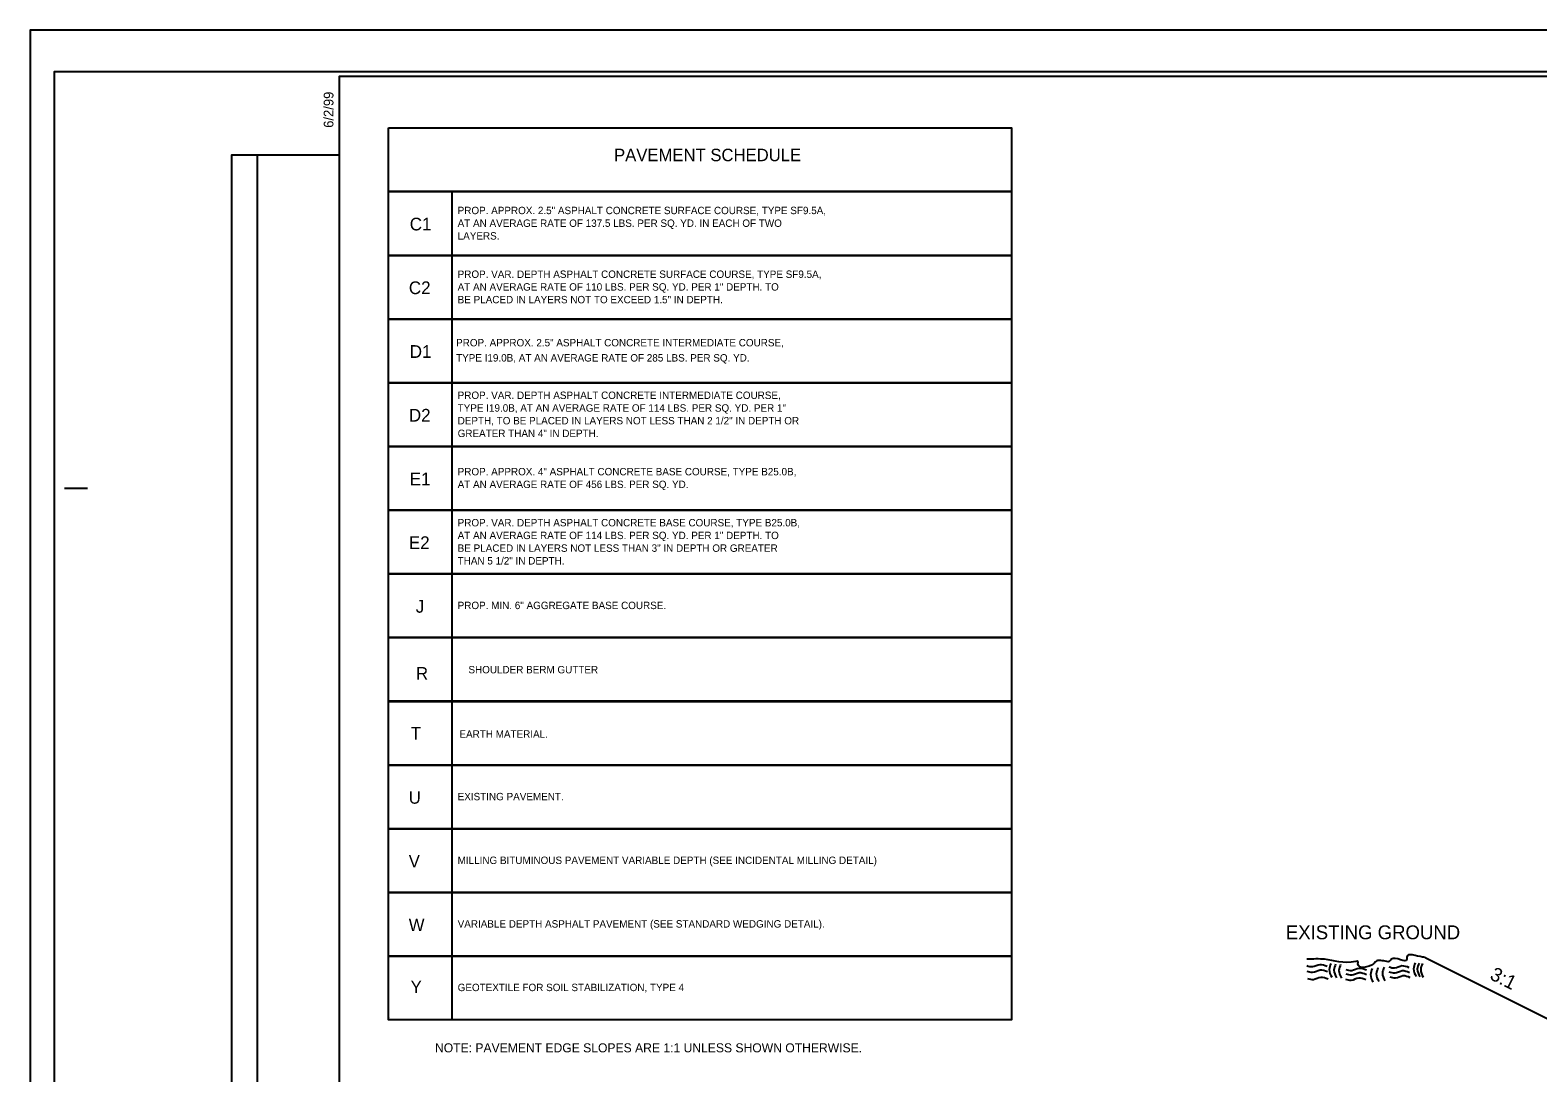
# Model space of a CAD drawing. Extents: x 575722 to 576066, y -53107 to -52774.
# Drawn here: x 575797.4 to 575878.8, y -53053.2 to -52996.9 of the extents above; entities that cross this region are included whole.
import ezdxf

# ---------------------------------------------------------------- set-up
doc = ezdxf.new("R2010")
doc.units = 0
for name, color, linetype in [('Old_Level_19', 7, 'Continuous'), ('Old_Level_2', 7, 'Continuous'), ('Prop DSN Text', 7, 'Continuous'), ('Prop Pavement Schedule Description CELL', 7, 'Continuous'), ('Sheet Block Revision CELL', 7, 'Continuous'), ('Sheet Cutting Line CELL', 7, 'Continuous'), ('Sheet Plot Border Inside CELL', 7, 'Continuous'), ('Sheet Plot Border Outside CELL', 7, 'Continuous'), ('Sheet Typical CELL', 7, 'Continuous'), ('Typical Slope Point Local CELL', 7, 'Continuous'), ('Typical Text Grade Point CELL', 7, 'Continuous')]:
    doc.layers.add(name, color=color, linetype=linetype)

# ---------------------------------------------------------------- blocks, each defined once
blk = doc.blocks.new('Note Standard Slope')
at = {"layer": 'Prop Pavement Schedule Description CELL'}
blk.add_line((0, 0), (0, 0), dxfattribs=at)
blk.add_text('NOTE: PAVEMENT EDGE SLOPES ARE 1:1 UNLESS SHOWN OTHERWISE.', height=5.4417, dxfattribs=at).set_placement((27.18, -20.66))

msp = doc.modelspace()

# ---------------------------------------------------------------- linework, layer by layer
at = {"layer": 'Old_Level_19'}
msp.add_lwpolyline([(575820.174, -53033.124), (575816.739, -53033.124), (575816.739, -53029.689), (575850.399, -53029.689), (575850.399, -53033.124), (575820.174, -53033.124), (575820.174, -53029.689)], dxfattribs=at)
at = {"layer": 'Old_Level_2'}
for points in [[(575872.735, -53046.963), (575872.592, -53046.948), (575871.752, -53046.948), (575871.752, -53047.068), (575870.912, -53047.068), (575870.792, -53047.188), (575870.672, -53047.188), (575870.072, -53047.188), (575869.952, -53047.308), (575869.112, -53047.308), (575869.112, -53047.188), (575868.992, -53047.188), (575867.312, -53047.068), (575866.356, -53047.068)], [(575867.444, -53047.456), (575867.055, -53047.362), (575866.651, -53047.483), (575866.356, -53047.429)], [(575867.653, -53047.301), (575867.559, -53047.624), (575867.693, -53048.041)], [(575867.908, -53047.328), (575867.814, -53047.651), (575867.949, -53048.068)], [(575868.177, -53047.342), (575868.083, -53047.664), (575868.217, -53048.081)], [(575869.568, -53047.658), (575869.178, -53047.564), (575868.775, -53047.684), (575868.479, -53047.631)], [(575869.884, -53047.57), (575869.79, -53047.893), (575869.924, -53048.309)], [(575870.193, -53047.53), (575870.099, -53047.852), (575870.233, -53048.269)], [(575870.529, -53047.489), (575870.435, -53047.812), (575870.569, -53048.229)], [(575871.88, -53047.523), (575871.49, -53047.429), (575871.087, -53047.55), (575870.791, -53047.496)], [(575872.209, -53047.261), (575872.115, -53047.584), (575872.249, -53048)], [(575872.411, -53047.274), (575872.317, -53047.597), (575872.451, -53048.014)], [(575872.599, -53047.301), (575872.505, -53047.624), (575872.639, -53048.041)], [(575867.458, -53047.752), (575867.068, -53047.658), (575866.665, -53047.779), (575866.369, -53047.725)], [(575867.498, -53048.141), (575867.108, -53048.047), (575866.705, -53048.168), (575866.409, -53048.115)], [(575869.541, -53048.182), (575869.151, -53048.088), (575868.748, -53048.209), (575868.452, -53048.155)], [(575869.568, -53047.9), (575869.178, -53047.805), (575868.775, -53047.926), (575868.479, -53047.873)], [(575871.893, -53047.792), (575871.503, -53047.698), (575871.1, -53047.819), (575870.805, -53047.765)], [(575871.934, -53048.061), (575871.544, -53047.967), (575871.141, -53048.088), (575870.845, -53048.034)]]:
    msp.add_spline(points, degree=3, dxfattribs=at)
at = {"layer": 'Prop Pavement Schedule Description CELL'}
msp.add_lwpolyline([(575816.739, -53002.148), (575850.4, -53002.148), (575850.4, -53005.591), (575816.739, -53005.591)], close=True, dxfattribs=at)
for points in [[(575820.182, -53009.034), (575816.739, -53009.034), (575816.739, -53005.591), (575850.399, -53005.591), (575850.399, -53009.034), (575820.182, -53009.034), (575820.182, -53005.591)], [(575820.182, -53012.476), (575816.739, -53012.476), (575816.739, -53009.034), (575850.399, -53009.034), (575850.399, -53012.476), (575820.182, -53012.476), (575820.182, -53009.034)], [(575820.182, -53015.919), (575816.739, -53015.919), (575816.739, -53012.476), (575850.399, -53012.476), (575850.399, -53015.919), (575820.182, -53015.919), (575820.182, -53012.476)], [(575820.182, -53019.361), (575816.739, -53019.361), (575816.739, -53015.919), (575850.4, -53015.919), (575850.4, -53019.361), (575820.182, -53019.361), (575820.182, -53015.919)], [(575820.182, -53022.804), (575816.739, -53022.804), (575816.739, -53019.361), (575850.399, -53019.361), (575850.399, -53022.804), (575820.182, -53022.804), (575820.182, -53019.361)], [(575820.182, -53026.246), (575816.739, -53026.246), (575816.739, -53022.804), (575850.399, -53022.804), (575850.399, -53026.246), (575820.182, -53026.246), (575820.182, -53022.804)], [(575820.182, -53029.689), (575816.739, -53029.689), (575816.739, -53026.246), (575850.399, -53026.246), (575850.399, -53029.689), (575820.182, -53029.689), (575820.182, -53026.246)], [(575820.182, -53036.573), (575816.739, -53036.573), (575816.739, -53033.131), (575850.399, -53033.131), (575850.399, -53036.573), (575820.182, -53036.573), (575820.182, -53033.131)], [(575820.182, -53040.016), (575816.739, -53040.016), (575816.739, -53036.573), (575850.399, -53036.573), (575850.399, -53040.016), (575820.182, -53040.016), (575820.182, -53036.573)], [(575820.182, -53043.458), (575816.739, -53043.458), (575816.739, -53040.016), (575850.399, -53040.016), (575850.399, -53043.458), (575820.182, -53043.458), (575820.182, -53040.016)], [(575820.182, -53046.901), (575816.739, -53046.901), (575816.739, -53043.458), (575850.4, -53043.458), (575850.4, -53046.901), (575820.182, -53046.901), (575820.182, -53043.458)], [(575820.182, -53050.343), (575816.739, -53050.343), (575816.739, -53046.901), (575850.4, -53046.901), (575850.4, -53050.343), (575820.182, -53050.343), (575820.182, -53046.901)]]:
    msp.add_lwpolyline(points, dxfattribs=at)
at = {"layer": 'Sheet Block Revision CELL'}
msp.add_line((575809.664, -53079.514), (575809.664, -53003.612), dxfattribs=at)
msp.add_lwpolyline([(575808.268, -53079.514), (575808.268, -53003.612), (575814.08, -53003.612), (575814.08, -53079.514)], close=True, dxfattribs=at)
at = {"layer": 'Sheet Cutting Line CELL'}
for p, q in [((575965.78, -52996.867), (575797.38, -52996.867)), ((575797.38, -52996.867), (575797.38, -53106.867))]:
    msp.add_line(p, q, dxfattribs=at)
at = {"layer": 'Sheet Plot Border Inside CELL'}
msp.add_lwpolyline([(575965.33, -52999.112), (575798.68, -52999.112), (575798.68, -53104.622), (575965.33, -53104.622)], close=True, dxfattribs=at)
at = {"layer": 'Sheet Plot Border Outside CELL'}
msp.add_lwpolyline([(575965.78, -52996.867), (575797.38, -52996.867), (575797.38, -53106.867), (575965.78, -53106.867)], close=True, dxfattribs=at)
at = {"layer": 'Sheet Typical CELL'}
msp.add_line((575799.23, -53021.617), (575800.48, -53021.617), dxfattribs=at)
msp.add_lwpolyline([(575964.08, -52999.367), (575814.08, -52999.367), (575814.08, -53104.367), (575964.08, -53104.367)], close=True, dxfattribs=at)
at = {"layer": 'Typical Slope Point Local CELL'}
msp.add_line((575872.735, -53046.963), (575880.664, -53050.928), dxfattribs=at)

# ---------------------------------------------------------------- block references
at = {"layer": 'Prop DSN Text', "xscale": 0.09000000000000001, "yscale": 0.09000000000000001}
msp.add_blockref('Note Standard Slope', (575816.805, -53050.236), dxfattribs=at)

# ---------------------------------------------------------------- texts
at = {"layer": 'Prop Pavement Schedule Description CELL'}
for s, height, p in [('PAVEMENT SCHEDULE', 0.6732, (575828.925, -53003.947)), ('PROP. APPROX. 2.5" ASPHALT CONCRETE SURFACE COURSE, TYPE SF9.5A, ', 0.3995, (575820.476, -53006.808)), ('C1', 0.6872, (575817.887, -53007.687)), ('AT AN AVERAGE RATE OF 137.5 LBS. PER SQ. YD. IN EACH OF TWO ', 0.3995, (575820.476, -53007.495)), ('LAYERS.', 0.3995, (575820.476, -53008.181)), ('PROP. VAR. DEPTH ASPHALT CONCRETE SURFACE COURSE, TYPE SF9.5A,', 0.3995, (575820.476, -53010.252)), ('C2', 0.6872, (575817.839, -53011.13)), ('AT AN AVERAGE RATE OF 110 LBS. PER SQ. YD. PER 1" DEPTH. TO', 0.3995, (575820.476, -53010.938)), ('BE PLACED IN LAYERS NOT TO EXCEED 1.5" IN DEPTH.', 0.3995, (575820.476, -53011.625)), ('D1', 0.6872, (575817.887, -53014.573)), ('PROP. APPROX. 2.5" ASPHALT CONCRETE INTERMEDIATE COURSE,', 0.3995, (575820.392, -53013.952)), ('TYPE I19.0B, AT AN AVERAGE RATE OF 285 LBS. PER SQ. YD.', 0.3995, (575820.392, -53014.771)), ('PROP. VAR. DEPTH ASPHALT CONCRETE INTERMEDIATE COURSE,', 0.3995, (575820.476, -53016.793)), ('D2', 0.6872, (575817.839, -53018.015)), ('TYPE I19.0B, AT AN AVERAGE RATE OF 114 LBS. PER SQ. YD. PER 1" ', 0.3995, (575820.476, -53017.479)), ('DEPTH, TO BE PLACED IN LAYERS NOT LESS THAN 2 1/2" IN DEPTH OR', 0.3995, (575820.476, -53018.166)), ('GREATER THAN 4" IN DEPTH.', 0.3995, (575820.476, -53018.852)), ('PROP. APPROX. 4" ASPHALT CONCRETE BASE COURSE, TYPE B25.0B,', 0.3995, (575820.476, -53020.919)), ('E1', 0.6872, (575817.887, -53021.458)), ('AT AN AVERAGE RATE OF 456 LBS. PER SQ. YD.', 0.3995, (575820.476, -53021.606)), ('AT AN AVERAGE RATE OF 114 LBS. PER SQ. YD. PER 1" DEPTH. TO', 0.3995, (575820.476, -53024.364)), ('PROP. VAR. DEPTH ASPHALT CONCRETE BASE COURSE, TYPE B25.0B,', 0.3995, (575820.476, -53023.678)), ('E2', 0.6872, (575817.839, -53024.9)), ('BE PLACED IN LAYERS NOT LESS THAN 3" IN DEPTH OR GREATER', 0.3995, (575820.476, -53025.051)), ('THAN 5 1/2" IN DEPTH.', 0.3995, (575820.476, -53025.737)), ('J', 0.687, (575818.212, -53028.343)), ('PROP. MIN. 6" AGGREGATE BASE COURSE.', 0.3995, (575820.476, -53028.147)), ('R', 0.673, (575818.227, -53031.953)), ('SHOULDER BERM GUTTER', 0.3995, (575821.058, -53031.617)), ('T ', 0.6732, (575817.946, -53035.195)), ('EARTH MATERIAL.', 0.3995, (575820.572, -53035.096)), ('U ', 0.6732, (575817.834, -53038.662)), ('EXISTING PAVEMENT.', 0.3995, (575820.476, -53038.475)), ('V ', 0.6732, (575817.834, -53042.105)), ('MILLING BITUMINOUS PAVEMENT VARIABLE DEPTH (SEE INCIDENTAL MILLING DETAIL)', 0.3995, (575820.476, -53041.917)), ('W ', 0.6732, (575817.834, -53045.547)), ('VARIABLE DEPTH ASPHALT PAVEMENT (SEE STANDARD WEDGING DETAIL).', 0.3995, (575820.476, -53045.353)), ('Y', 0.673, (575817.936, -53048.894)), ('GEOTEXTILE FOR SOIL STABILIZATION, TYPE 4', 0.3995, (575820.476, -53048.787))]:
    msp.add_text(s, height=height, dxfattribs=at).set_placement(p)
at = {"layer": 'Sheet Typical CELL'}
msp.add_text('6/2/99', height=0.525, rotation=90, dxfattribs=at).set_placement((575813.765, -53002.142))
at = {"layer": 'Typical Slope Point Local CELL'}
msp.add_text('3:1', height=0.75, rotation=333.43495, dxfattribs=at).set_placement((575876.186, -53048.116))
at = {"layer": 'Typical Text Grade Point CELL'}
msp.add_text('EXISTING GROUND', height=0.75, dxfattribs=at).set_placement((575865.216, -53045.984))

doc.saveas('drawing.dxf')
